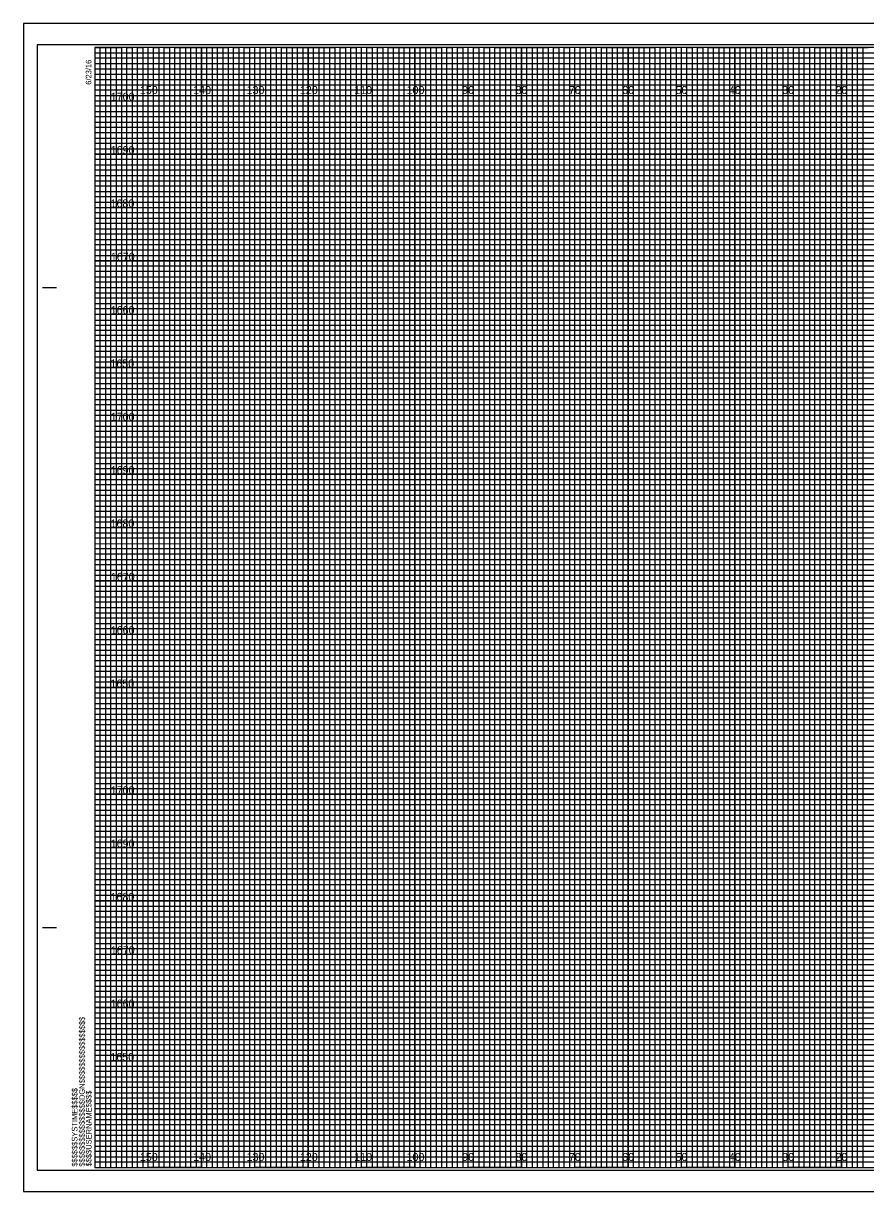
# Model space of a CAD drawing. Extents: x 656 to 993, y -2 to 2857.
# Drawn here: x 656.3 to 814.2, y 1098.3 to 1317.3 of the extents above; entities that cross this region are included whole.
import ezdxf

# ---------------------------------------------------------------- set-up
doc = ezdxf.new("R2010")
doc.units = 0
for name, color, linetype in [('Prop RDY Alternate Text Blue', 7, 'Continuous'), ('Prop Retaining Wall', 7, 'Continuous'), ('Prop SS Cut Line', 7, 'Continuous'), ('Prop SS Fill Line', 7, 'Continuous'), ('Prop SS Transition Line', 7, 'Continuous'), ('Raster_Level_0', 7, 'Continuous'), ('Raster_Level_3', 7, 'Continuous'), ('Scratch_Level_3', 7, 'Continuous'), ('Scratch_Level_7', 7, 'Continuous'), ('Typical Guardrail CELL', 7, 'Continuous'), ('Typical Text Asphalt at Bridge Approach CELL', 7, 'Continuous')]:
    doc.layers.add(name, color=color, linetype=linetype)

msp = doc.modelspace()

# ---------------------------------------------------------------- linework, layer by layer
at = {"layer": 'Prop RDY Alternate Text Blue'}
for p, q in [((679.74, 1102.8), (679.74, 1312.8)), ((689.74, 1102.8), (689.74, 1312.8)), ((699.74, 1102.8), (699.74, 1312.8)), ((709.74, 1102.8), (709.74, 1312.8)), ((719.74, 1102.8), (719.74, 1312.8)), ((729.74, 1102.8), (729.74, 1312.8)), ((739.74, 1102.8), (739.74, 1312.8)), ((749.74, 1102.8), (749.74, 1312.8)), ((759.74, 1102.8), (759.74, 1312.8)), ((769.74, 1102.8), (769.74, 1312.8)), ((779.74, 1102.8), (779.74, 1312.8)), ((789.74, 1102.8), (789.74, 1312.8)), ((799.74, 1102.8), (799.74, 1312.8)), ((809.74, 1102.8), (809.74, 1312.8)), ((669.74, 1302.8), (989.74, 1302.8)), ((669.74, 1292.8), (989.74, 1292.8)), ((669.74, 1282.8), (989.74, 1282.8)), ((669.74, 1272.8), (989.74, 1272.8)), ((669.74, 1262.8), (989.74, 1262.8)), ((669.74, 1252.8), (989.74, 1252.8)), ((669.74, 1242.8), (989.74, 1242.8)), ((669.74, 1232.8), (989.74, 1232.8)), ((669.74, 1222.8), (989.74, 1222.8)), ((669.74, 1212.8), (989.74, 1212.8)), ((669.74, 1202.8), (989.74, 1202.8)), ((669.74, 1192.8), (989.74, 1192.8)), ((669.74, 1182.8), (989.74, 1182.8)), ((669.74, 1172.8), (989.74, 1172.8)), ((669.74, 1162.8), (989.74, 1162.8)), ((669.74, 1152.8), (989.74, 1152.8)), ((669.74, 1142.8), (989.74, 1142.8)), ((669.74, 1132.8), (989.74, 1132.8)), ((669.74, 1122.8), (989.74, 1122.8)), ((669.74, 1112.8), (989.74, 1112.8))]:
    msp.add_line(p, q, dxfattribs=at)
at = {"layer": 'Prop Retaining Wall'}
for p, q in [((659.94, 1267.8), (662.44, 1267.8)), ((660.04, 1267.8), (662.54, 1267.8)), ((659.94, 1147.8), (662.44, 1147.8)), ((660.04, 1147.8), (662.54, 1147.8)), ((669.74, 1102.8), (669.74, 1102.8)), ((669.74, 1102.8), (669.74, 1102.8)), ((669.74, 1102.8), (669.74, 1102.8)), ((669.74, 1102.8), (669.74, 1102.8)), ((669.74, 1102.8), (669.74, 1102.8)), ((669.74, 1102.8), (669.74, 1102.8)), ((669.74, 1102.8), (669.74, 1102.8))]:
    msp.add_line(p, q, dxfattribs=at)
msp.add_lwpolyline([(989.74, 1312.8), (669.74, 1312.8), (669.74, 1102.8), (989.74, 1102.8)], close=True, dxfattribs=at)
at = {"layer": 'Prop SS Cut Line'}
for points in [[(669.74, 1312.8), (674.74, 1312.8), (674.74, 1102.8), (684.74, 1102.8), (684.74, 1312.8), (694.74, 1312.8), (694.74, 1102.8), (704.74, 1102.8), (704.74, 1312.8), (714.74, 1312.8), (714.74, 1102.8), (724.74, 1102.8), (724.74, 1312.8), (734.74, 1312.8), (734.74, 1102.8), (744.74, 1102.8), (744.74, 1312.8), (754.74, 1312.8), (754.74, 1102.8), (764.74, 1102.8), (764.74, 1312.8), (774.74, 1312.8), (774.74, 1102.8), (784.74, 1102.8), (784.74, 1312.8), (794.74, 1312.8), (794.74, 1102.8), (804.74, 1102.8), (804.74, 1312.8), (814.74, 1312.8)], [(669.74, 1307.8), (944.74, 1307.8)], [(669.74, 1287.8), (989.74, 1287.8), (989.74, 1297.8), (669.74, 1297.8)], [(669.74, 1267.8), (989.74, 1267.8), (989.74, 1277.8), (669.74, 1277.8)], [(669.74, 1247.8), (989.74, 1247.8), (989.74, 1257.8), (669.74, 1257.8)], [(669.74, 1227.8), (989.74, 1227.8), (989.74, 1237.8), (669.74, 1237.8)], [(669.74, 1207.8), (989.74, 1207.8), (989.74, 1217.8), (669.74, 1217.8)], [(669.74, 1187.8), (989.74, 1187.8), (989.74, 1197.8), (669.74, 1197.8)], [(669.74, 1167.8), (989.74, 1167.8), (989.74, 1177.8), (669.74, 1177.8)], [(669.74, 1147.8), (989.74, 1147.8), (989.74, 1157.8), (669.74, 1157.8)], [(669.74, 1127.8), (989.74, 1127.8), (989.74, 1137.8), (669.74, 1137.8)], [(669.74, 1107.8), (989.74, 1107.8), (989.74, 1117.8), (669.74, 1117.8)]]:
    msp.add_lwpolyline(points, dxfattribs=at)
at = {"layer": 'Prop SS Fill Line'}
for p, q in [((679.74, 1312.8), (669.74, 1312.8)), ((679.74, 1102.8), (679.74, 1312.8)), ((699.74, 1312.8), (689.74, 1312.8)), ((689.74, 1312.8), (689.74, 1102.8)), ((699.74, 1102.8), (699.74, 1312.8)), ((719.74, 1312.8), (709.74, 1312.8)), ((709.74, 1312.8), (709.74, 1102.8)), ((719.74, 1102.8), (719.74, 1312.8)), ((739.74, 1312.8), (729.74, 1312.8)), ((729.74, 1312.8), (729.74, 1102.8)), ((739.74, 1102.8), (739.74, 1312.8)), ((759.74, 1312.8), (749.74, 1312.8)), ((749.74, 1312.8), (749.74, 1102.8)), ((759.74, 1102.8), (759.74, 1312.8)), ((779.74, 1312.8), (769.74, 1312.8)), ((769.74, 1312.8), (769.74, 1102.8)), ((779.74, 1102.8), (779.74, 1312.8)), ((799.74, 1312.8), (789.74, 1312.8)), ((789.74, 1312.8), (789.74, 1102.8)), ((799.74, 1102.8), (799.74, 1312.8)), ((819.74, 1312.8), (809.74, 1312.8)), ((809.74, 1312.8), (809.74, 1102.8)), ((689.74, 1102.8), (679.74, 1102.8)), ((709.74, 1102.8), (699.74, 1102.8)), ((729.74, 1102.8), (719.74, 1102.8)), ((749.74, 1102.8), (739.74, 1102.8)), ((769.74, 1102.8), (759.74, 1102.8)), ((789.74, 1102.8), (779.74, 1102.8)), ((809.74, 1102.8), (799.74, 1102.8))]:
    msp.add_line(p, q, dxfattribs=at)
for points in [[(669.74, 1302.8), (989.74, 1302.8), (989.74, 1292.8), (669.74, 1292.8)], [(669.74, 1282.8), (989.74, 1282.8), (989.74, 1272.8), (669.74, 1272.8)], [(669.74, 1262.8), (989.74, 1262.8), (989.74, 1252.8), (669.74, 1252.8)], [(669.74, 1242.8), (989.74, 1242.8), (989.74, 1232.8), (669.74, 1232.8)], [(669.74, 1222.8), (989.74, 1222.8), (989.74, 1212.8), (669.74, 1212.8)], [(669.74, 1202.8), (989.74, 1202.8), (989.74, 1192.8), (669.74, 1192.8)], [(669.74, 1182.8), (989.74, 1182.8), (989.74, 1172.8), (669.74, 1172.8)], [(669.74, 1162.8), (989.74, 1162.8), (989.74, 1152.8), (669.74, 1152.8)], [(669.74, 1142.8), (989.74, 1142.8), (989.74, 1132.8), (669.74, 1132.8)], [(669.74, 1122.8), (989.74, 1122.8), (989.74, 1112.8), (669.74, 1112.8)]]:
    msp.add_lwpolyline(points, dxfattribs=at)
at = {"layer": 'Prop SS Transition Line'}
for p, q in [((669.74, 1311.8), (929.74, 1311.8)), ((929.74, 1310.78), (669.74, 1310.78)), ((669.74, 1310.78), (669.74, 1309.8)), ((669.74, 1309.8), (929.74, 1309.8)), ((929.74, 1308.69), (669.74, 1308.69)), ((669.74, 1308.69), (669.74, 1306.8)), ((669.74, 1306.8), (989.74, 1306.8))]:
    msp.add_line(p, q, dxfattribs=at)
for points in [[(669.74, 1305.8), (939.74, 1305.8), (989.74, 1305.8), (989.74, 1304.8), (669.74, 1304.8)], [(669.74, 1303.8), (989.74, 1303.8), (989.74, 1301.8), (669.74, 1301.8)], [(669.74, 1300.8), (989.74, 1300.8), (989.74, 1299.8), (669.74, 1299.78)], [(669.74, 1298.8), (989.74, 1298.8), (989.74, 1296.8), (669.74, 1296.8)], [(669.74, 1295.8), (989.74, 1295.8), (989.74, 1294.8), (669.74, 1294.8)], [(669.74, 1293.8), (989.74, 1293.8), (989.74, 1291.8), (669.74, 1291.8)], [(669.74, 1290.8), (989.74, 1290.8), (989.74, 1289.8), (669.74, 1289.8)], [(669.74, 1288.8), (989.74, 1288.8), (989.74, 1286.8), (669.74, 1286.8)], [(669.74, 1285.8), (989.74, 1285.8), (989.74, 1284.8), (669.74, 1284.8)], [(669.74, 1283.8), (989.74, 1283.8), (989.74, 1281.8), (669.74, 1281.8)], [(669.74, 1280.8), (989.74, 1280.8), (989.74, 1279.8), (669.74, 1279.8)], [(669.74, 1278.8), (989.74, 1278.8), (989.74, 1276.75), (989.74, 1275.8), (989.74, 1274.8), (669.74, 1274.8)], [(669.74, 1276.8), (989.74, 1276.8), (989.74, 1275.8), (669.74, 1275.8)], [(669.74, 1273.8), (989.74, 1273.8), (989.74, 1271.8), (669.74, 1271.83)], [(669.74, 1271.83), (989.74, 1271.8), (989.74, 1270.8), (669.74, 1270.8)], [(669.74, 1269.8), (989.74, 1269.8), (989.74, 1268.8), (669.74, 1268.8)], [(669.74, 1266.8), (989.74, 1266.8), (989.74, 1265.8), (669.74, 1265.8)], [(669.74, 1264.8), (989.74, 1264.8), (989.74, 1263.8), (669.74, 1263.8)], [(669.67, 1261.69), (989.74, 1261.69), (989.74, 1260.68), (669.67, 1260.68)], [(669.74, 1259.8), (989.74, 1259.8), (989.74, 1258.8), (669.74, 1258.8)], [(669.74, 1256.8), (989.74, 1256.8), (989.74, 1255.8), (669.74, 1255.8)], [(669.74, 1254.8), (989.74, 1254.8), (989.74, 1253.8), (669.74, 1253.8)], [(669.74, 1251.8), (989.74, 1251.8), (989.74, 1250.8), (669.74, 1250.8)], [(669.74, 1249.8), (989.74, 1249.8), (989.74, 1248.8), (669.74, 1248.8)], [(669.74, 1246.8), (989.74, 1246.8), (989.74, 1245.8), (669.74, 1245.8)], [(669.74, 1244.8), (989.74, 1244.8), (989.74, 1243.8), (669.74, 1243.8)], [(669.74, 1241.8), (989.74, 1241.8), (989.73, 1240.78), (669.74, 1240.8)], [(669.74, 1239.8), (989.74, 1239.8), (989.74, 1238.8), (669.74, 1238.8)], [(669.74, 1236.8), (989.74, 1236.8), (989.74, 1235.8), (669.74, 1235.8)], [(669.74, 1234.8), (989.74, 1234.8), (989.74, 1233.8), (669.74, 1233.8)], [(669.74, 1231.8), (989.74, 1231.8), (989.74, 1230.8), (669.74, 1230.8)], [(669.74, 1229.8), (989.74, 1229.8), (989.74, 1228.8), (669.74, 1228.8)], [(669.74, 1226.8), (989.74, 1226.8), (989.74, 1225.8), (669.74, 1225.8)], [(669.74, 1224.8), (989.74, 1224.8), (989.74, 1223.8), (669.74, 1223.8)], [(669.74, 1221.8), (989.74, 1221.8), (989.74, 1220.8), (669.74, 1220.8)], [(669.74, 1219.79), (989.81, 1219.71), (989.74, 1218.8), (669.74, 1218.8)], [(669.74, 1216.8), (989.74, 1216.8), (989.74, 1215.8), (669.74, 1215.8)], [(669.74, 1214.8), (989.74, 1214.8), (989.74, 1213.8), (669.74, 1213.8)], [(669.74, 1211.8), (989.74, 1211.8), (989.74, 1210.8), (669.74, 1210.8)], [(669.74, 1209.8), (989.74, 1209.8), (989.74, 1208.8), (669.74, 1208.8)], [(669.74, 1206.8), (989.74, 1206.8), (989.74, 1205.8), (669.74, 1205.8)], [(669.74, 1204.8), (989.74, 1204.8), (989.74, 1203.8), (669.74, 1203.8)], [(669.74, 1201.8), (989.74, 1201.8), (989.74, 1200.8), (669.74, 1200.8)], [(669.74, 1199.8), (989.74, 1199.8), (989.74, 1198.8), (669.74, 1198.8)], [(669.74, 1196.8), (989.74, 1196.8), (989.74, 1195.8), (669.74, 1195.8)], [(669.74, 1194.8), (989.74, 1194.8), (989.74, 1193.8), (669.74, 1193.8)], [(669.74, 1191.8), (989.74, 1191.8), (989.74, 1190.8), (669.74, 1190.8)], [(669.74, 1189.8), (989.74, 1189.8), (989.74, 1188.8), (669.74, 1188.8)], [(669.74, 1186.8), (989.74, 1186.8), (989.74, 1185.8), (669.74, 1185.8)], [(669.74, 1184.8), (989.74, 1184.8), (989.74, 1183.8), (669.74, 1183.8)], [(669.74, 1181.8), (989.74, 1181.8), (989.73, 1180.78), (669.74, 1180.8)], [(669.74, 1179.8), (989.74, 1179.8), (989.74, 1178.8), (669.74, 1178.8)], [(669.74, 1176.8), (989.74, 1176.8), (989.74, 1175.8), (669.74, 1175.8)], [(669.74, 1174.8), (989.74, 1174.8), (989.74, 1173.8), (669.74, 1173.8)], [(669.74, 1171.8), (989.74, 1171.8), (989.74, 1170.8), (669.74, 1170.8)], [(669.74, 1169.8), (989.74, 1169.8), (989.74, 1168.8), (669.74, 1168.8)], [(669.74, 1166.8), (989.74, 1166.8), (989.74, 1165.8), (669.74, 1165.8)], [(669.74, 1164.8), (989.74, 1164.8), (989.74, 1163.8), (669.74, 1163.8)], [(669.74, 1161.8), (989.74, 1161.8), (989.74, 1160.8), (669.74, 1160.8)], [(669.74, 1159.79), (989.81, 1159.71), (989.74, 1158.8), (669.74, 1158.8)], [(669.74, 1156.8), (989.74, 1156.8), (989.74, 1155.8), (669.74, 1155.8)], [(669.74, 1154.8), (989.74, 1154.8), (989.74, 1153.8), (669.74, 1153.8)], [(669.74, 1151.8), (989.74, 1151.8), (989.74, 1150.8), (669.74, 1150.8)], [(669.74, 1149.8), (989.74, 1149.8), (989.74, 1148.8), (669.74, 1148.8)], [(669.74, 1146.8), (989.74, 1146.8), (989.74, 1145.8), (669.74, 1145.8)], [(669.74, 1144.8), (989.74, 1144.8), (989.74, 1143.8), (669.74, 1143.8)], [(669.74, 1141.8), (989.74, 1141.8), (989.74, 1140.8), (669.74, 1140.8)], [(669.74, 1139.8), (989.74, 1139.8), (989.74, 1138.8), (669.74, 1138.8)], [(669.74, 1136.8), (989.74, 1136.8), (989.74, 1135.8), (669.74, 1135.8)], [(669.74, 1134.8), (989.74, 1134.8), (989.74, 1133.8), (669.74, 1133.8)], [(669.74, 1131.8), (989.74, 1131.8), (989.74, 1130.8), (669.74, 1130.8)], [(669.74, 1129.8), (989.74, 1129.8), (989.74, 1128.8), (669.74, 1128.8)], [(669.74, 1126.8), (989.74, 1126.8), (989.74, 1125.8), (669.74, 1125.8)], [(669.74, 1124.8), (989.74, 1124.8), (989.74, 1123.8), (669.74, 1123.8)], [(669.74, 1121.8), (989.74, 1121.8), (989.74, 1120.8), (669.74, 1120.8)], [(669.74, 1119.8), (989.74, 1119.8), (989.74, 1118.8), (669.74, 1118.8)], [(669.74, 1116.8), (989.74, 1116.8), (989.74, 1115.8), (669.74, 1115.8)], [(669.74, 1114.8), (989.74, 1114.8), (989.74, 1113.8), (669.74, 1113.8)], [(669.74, 1111.8), (989.74, 1111.8), (989.74, 1110.8), (669.74, 1110.8)], [(669.74, 1109.8), (989.74, 1109.8), (989.74, 1108.8), (669.74, 1108.8)], [(669.74, 1106.8), (989.74, 1106.8), (989.74, 1105.8), (669.74, 1105.8)], [(669.74, 1104.8), (989.74, 1104.8), (989.74, 1103.8), (669.74, 1103.8)]]:
    msp.add_lwpolyline(points, dxfattribs=at)
at = {"layer": 'Raster_Level_3'}
for points in [[(669.74, 1102.8), (670.74, 1102.8), (670.74, 1312.8), (671.74, 1312.8), (671.74, 1102.8)], [(671.74, 1102.8), (672.74, 1102.8), (672.74, 1312.8), (673.74, 1312.8), (673.74, 1102.8)], [(674.74, 1102.8), (675.74, 1102.8), (675.74, 1312.8), (676.74, 1312.8), (676.74, 1102.8)], [(676.74, 1102.8), (677.74, 1102.8), (677.74, 1312.8), (678.74, 1312.8), (678.74, 1102.8)], [(679.74, 1102.8), (680.74, 1102.8), (680.74, 1312.8), (681.74, 1312.8), (681.74, 1102.8)], [(681.74, 1102.8), (682.74, 1102.8), (682.74, 1312.8), (683.74, 1312.8), (683.74, 1102.8)], [(684.74, 1102.8), (685.74, 1102.8), (685.74, 1312.8), (686.74, 1312.8), (686.74, 1102.8)], [(686.74, 1102.8), (687.74, 1102.8), (687.74, 1312.8), (688.74, 1312.8), (688.74, 1102.8)], [(689.74, 1102.8), (690.74, 1102.8), (690.74, 1312.8), (691.74, 1312.8), (691.74, 1102.8)], [(691.74, 1102.8), (692.74, 1102.8), (692.74, 1312.8), (693.74, 1312.8), (693.74, 1102.8)], [(694.74, 1102.8), (695.74, 1102.8), (695.74, 1312.8), (696.74, 1312.8), (696.74, 1102.8)], [(696.74, 1102.8), (697.74, 1102.8), (697.74, 1312.8), (698.74, 1312.8), (698.74, 1102.8)], [(699.74, 1102.8), (700.74, 1102.8), (700.74, 1312.8), (701.74, 1312.8), (701.74, 1102.8)], [(701.74, 1102.8), (702.74, 1102.8), (702.74, 1312.8), (703.74, 1312.8), (703.74, 1102.8)], [(704.74, 1102.8), (705.74, 1102.8), (705.74, 1312.8), (706.74, 1312.8), (706.74, 1102.8)], [(706.74, 1102.8), (707.74, 1102.8), (707.74, 1312.8), (708.74, 1312.8), (708.74, 1102.8)], [(709.74, 1102.8), (710.74, 1102.8), (710.74, 1312.8), (711.74, 1312.8), (711.74, 1102.8)], [(711.74, 1102.8), (712.74, 1102.8), (712.74, 1312.8), (713.74, 1312.8), (713.74, 1102.8)], [(714.74, 1102.8), (715.74, 1102.8), (715.74, 1312.8), (716.74, 1312.8), (716.74, 1102.8)], [(716.74, 1102.8), (717.74, 1102.8), (717.74, 1312.8), (718.74, 1312.8), (718.74, 1102.8)], [(719.74, 1102.8), (720.74, 1102.8), (720.74, 1312.8), (721.74, 1312.8), (721.74, 1102.8)], [(721.74, 1102.8), (722.74, 1102.8), (722.74, 1312.8), (723.74, 1312.8), (723.74, 1102.8)], [(724.74, 1102.8), (725.74, 1102.8), (725.74, 1312.8), (726.74, 1312.8), (726.74, 1102.8)], [(726.74, 1102.8), (727.74, 1102.8), (727.74, 1312.8), (728.74, 1312.8), (728.74, 1102.8)], [(729.74, 1102.8), (730.74, 1102.8), (730.74, 1312.8), (731.74, 1312.8), (731.74, 1102.8)], [(731.74, 1102.8), (732.74, 1102.8), (732.74, 1312.8), (733.74, 1312.8), (733.74, 1102.8)], [(734.74, 1102.8), (735.74, 1102.8), (735.74, 1312.8), (736.74, 1312.8), (736.74, 1102.8)], [(736.74, 1102.8), (737.74, 1102.8), (737.74, 1312.8), (738.74, 1312.8), (738.74, 1102.8)], [(739.74, 1102.8), (740.74, 1102.8), (740.74, 1312.8), (741.74, 1312.8), (741.74, 1102.8)], [(741.74, 1102.8), (742.74, 1102.8), (742.74, 1312.8), (743.74, 1312.8), (743.74, 1102.8)], [(744.74, 1102.8), (745.74, 1102.8), (745.74, 1312.8), (746.74, 1312.8), (746.74, 1102.8)], [(746.74, 1102.8), (747.74, 1102.8), (747.74, 1312.8), (748.74, 1312.8), (748.74, 1102.8)], [(749.74, 1102.8), (750.74, 1102.8), (750.74, 1312.8), (751.74, 1312.8), (751.74, 1102.8)], [(751.74, 1102.8), (752.74, 1102.8), (752.74, 1312.8), (753.74, 1312.8), (753.74, 1102.8)], [(754.74, 1102.8), (755.74, 1102.8), (755.74, 1312.8), (756.74, 1312.8), (756.74, 1102.8)], [(756.74, 1102.8), (757.74, 1102.8), (757.74, 1312.8), (758.74, 1312.8), (758.74, 1102.8)], [(759.74, 1102.8), (760.74, 1102.8), (760.74, 1312.8), (761.74, 1312.8), (761.74, 1102.8)], [(761.74, 1102.8), (762.74, 1102.8), (762.74, 1312.8), (763.74, 1312.8), (763.74, 1102.8)], [(764.74, 1102.8), (765.74, 1102.8), (765.74, 1312.8), (766.74, 1312.8), (766.74, 1102.8)], [(766.74, 1102.8), (767.74, 1102.8), (767.74, 1312.8), (768.74, 1312.8), (768.74, 1102.8)], [(769.74, 1102.8), (770.74, 1102.8), (770.74, 1312.8), (771.74, 1312.8), (771.74, 1102.8)], [(771.74, 1102.8), (772.74, 1102.8), (772.74, 1312.8), (773.74, 1312.8), (773.74, 1102.8)], [(774.74, 1102.8), (775.74, 1102.8), (775.74, 1312.8), (776.74, 1312.8), (776.74, 1102.8)], [(776.74, 1102.8), (777.74, 1102.8), (777.74, 1312.8), (778.74, 1312.8), (778.74, 1102.8)], [(779.74, 1102.8), (780.74, 1102.8), (780.74, 1312.8), (781.74, 1312.8), (781.74, 1102.8)], [(781.74, 1102.8), (782.74, 1102.8), (782.74, 1312.8), (783.74, 1312.8), (783.74, 1102.8)], [(784.74, 1102.8), (785.74, 1102.8), (785.74, 1312.8), (786.74, 1312.8), (786.74, 1102.8)], [(786.74, 1102.8), (787.74, 1102.8), (787.74, 1312.8), (788.74, 1312.8), (788.74, 1102.8)], [(789.74, 1102.8), (790.74, 1102.8), (790.74, 1312.8), (791.74, 1312.8), (791.74, 1102.8)], [(791.74, 1102.8), (792.74, 1102.8), (792.74, 1312.8), (793.74, 1312.8), (793.74, 1102.8)], [(794.74, 1102.8), (795.74, 1102.8), (795.74, 1312.8), (796.74, 1312.8), (796.74, 1102.8)], [(796.74, 1102.8), (797.74, 1102.8), (797.74, 1312.8), (798.74, 1312.8), (798.74, 1102.8)], [(799.74, 1102.8), (800.74, 1102.8), (800.74, 1312.8), (801.74, 1312.8), (801.74, 1102.8)], [(801.74, 1102.8), (802.74, 1102.8), (802.74, 1312.8), (803.74, 1312.8), (803.74, 1102.8)], [(804.74, 1102.8), (805.74, 1102.8), (805.74, 1312.8), (806.74, 1312.8), (806.74, 1102.8)], [(806.74, 1102.8), (807.74, 1102.8), (807.74, 1312.8), (808.74, 1312.8), (808.74, 1102.8)], [(809.74, 1102.8), (810.74, 1102.8), (810.74, 1312.8), (811.74, 1312.8), (811.74, 1102.8)], [(811.74, 1102.8), (812.74, 1102.8), (812.74, 1312.8), (813.74, 1312.8), (813.74, 1102.8)]]:
    msp.add_lwpolyline(points, dxfattribs=at)
at = {"layer": 'Scratch_Level_7'}
msp.add_lwpolyline([(656.34, 1098.3), (993.04, 1098.3), (993.04, 1317.3), (656.34, 1317.3)], close=True, dxfattribs=at)
at = {"layer": 'Typical Guardrail CELL'}
msp.add_lwpolyline([(658.94, 1102.3), (992.14, 1102.3), (992.14, 1313.3), (658.94, 1313.3)], close=True, dxfattribs=at)
at = {"layer": 'Typical Text Asphalt at Bridge Approach CELL'}
for p, q in [((993.04, 1317.3), (656.34, 1317.3)), ((656.34, 1317.3), (656.34, 1098.3)), ((656.34, 1098.3), (993.04, 1098.3))]:
    msp.add_line(p, q, dxfattribs=at)

# ---------------------------------------------------------------- texts
at = {"layer": 'Prop Retaining Wall'}
for s, p in [('6/23/16', (669.09, 1305.8)), ('$$$$$$$$$$$$$$$$DGN$$$$$$$$$$$$$$$$', (667.86, 1102.98)), ('$$$$$$SYSTIME$$$$$', (666.48, 1102.98)), ('$$$$USERNAME$$$$', (669.12, 1103.03))]:
    msp.add_text(s, height=1.05, rotation=90, dxfattribs=at).set_placement(p)
at = {"layer": 'Raster_Level_0'}
for s, p in [('150', (678.18, 1304.05)), ('140', (688.18, 1304.05)), ('130', (698.18, 1304.05)), ('120', (708.18, 1304.05)), ('110', (718.36, 1304.05)), ('100', (728.18, 1304.05)), ('90', (738.6, 1304.05)), ('80', (748.6, 1304.05)), ('70', (758.6, 1304.05)), ('60', (768.6, 1304.05)), ('50', (778.6, 1304.05)), ('40', (788.6, 1304.05)), ('30', (798.6, 1304.05)), ('20', (808.6, 1304.05)), ('150', (678.18, 1104.05)), ('140', (688.18, 1104.05)), ('130', (698.18, 1104.05)), ('120', (708.18, 1104.05)), ('110', (718.36, 1104.05)), ('100', (728.18, 1104.05)), ('90', (738.6, 1104.05)), ('80', (748.6, 1104.05)), ('70', (758.6, 1104.05)), ('60', (768.6, 1104.05)), ('50', (778.6, 1104.05)), ('40', (788.6, 1104.05)), ('30', (798.6, 1104.05)), ('20', (808.6, 1104.05))]:
    msp.add_text(s, height=1.5, dxfattribs=at).set_placement(p)
at = {"layer": 'Scratch_Level_3'}
for s, p in [('1700', (672.72, 1302.8)), ('1690', (672.71, 1292.8)), ('1680', (672.68, 1282.8)), ('1670', (672.74, 1272.8)), ('1660', (672.71, 1262.8)), ('1650', (672.66, 1252.8)), ('1700', (672.72, 1242.8)), ('1690', (672.71, 1232.8)), ('1680', (672.68, 1222.8)), ('1670', (672.74, 1212.8)), ('1660', (672.71, 1202.8)), ('1650', (672.66, 1192.8)), ('1700', (672.72, 1172.8)), ('1690', (672.71, 1162.8)), ('1680', (672.68, 1152.8)), ('1670', (672.74, 1142.8)), ('1660', (672.71, 1132.8)), ('1650', (672.66, 1122.8))]:
    msp.add_text(s, height=1.5, dxfattribs=at).set_placement(p)

doc.saveas('drawing.dxf')
